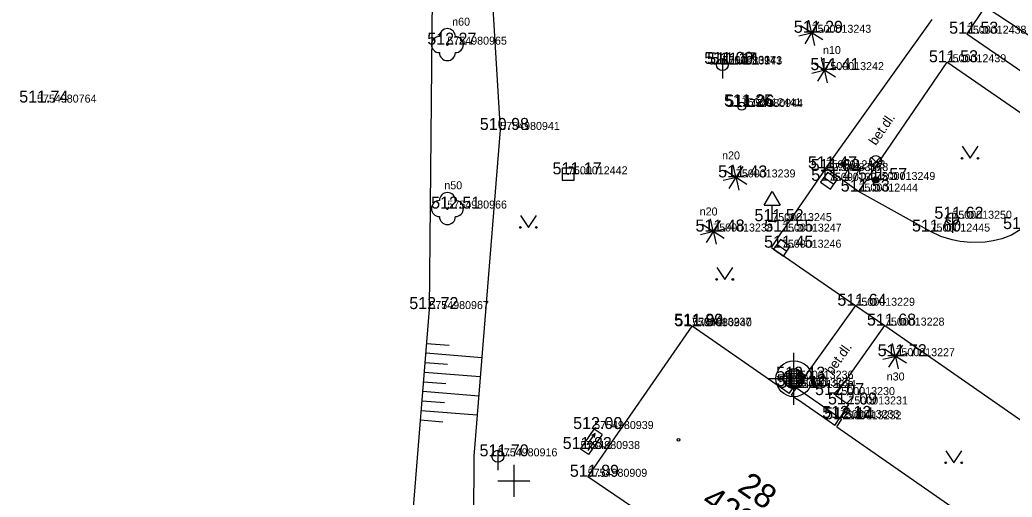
# Model space of a CAD drawing. Extents: x -669251 to -668549, y -1128351 to -1127698.
# Drawn here: x -669030.9 to -668968.9, y -1127851 to -1127821.2 of the extents above; entities that cross this region are included whole.
import ezdxf

# ---------------------------------------------------------------- set-up
doc = ezdxf.new("R2010")
doc.units = 0
for name, color, linetype in [('Vrstva 1', 7, 'Continuous'), ('Vrstva 10', 7, 'Continuous'), ('Vrstva 14', 7, 'Continuous'), ('Vrstva 15', 7, 'Continuous'), ('Vrstva 2', 7, 'Continuous'), ('Vrstva 22', 7, 'Continuous'), ('Vrstva 24', 7, 'Continuous'), ('Vrstva 26', 7, 'Continuous'), ('Vrstva 27', 7, 'Continuous'), ('Vrstva 28', 7, 'Continuous'), ('Vrstva 3', 7, 'Continuous'), ('Vrstva 33', 7, 'Continuous'), ('Vrstva 34', 7, 'Continuous'), ('Vrstva 35', 7, 'Continuous'), ('Vrstva 36', 7, 'Continuous'), ('Vrstva 40', 7, 'Continuous'), ('Vrstva 43', 7, 'Continuous'), ('Vrstva 44', 7, 'Continuous'), ('Vrstva 47', 7, 'Continuous'), ('Vrstva 5', 7, 'Continuous'), ('Vrstva 58', 7, 'Continuous'), ('Vrstva 6', 7, 'Continuous'), ('Vrstva 61', 7, 'Continuous')]:
    doc.layers.add(name, color=color, linetype=linetype)

msp = doc.modelspace()

# ---------------------------------------------------------------- linework, layer by layer
at = {"layer": 'Vrstva 1'}
for p, q in [((-668981.406, -1127822.003), (-668981.406, -1127822.003)), ((-668971.708, -1127822.059), (-668971.708, -1127822.059)), ((-669004.161, -1127822.744), (-669004.161, -1127822.744)), ((-668986.979, -1127823.945), (-668986.979, -1127823.945)), ((-668986.976, -1127823.985), (-668986.976, -1127823.985)), ((-668986.967, -1127823.978), (-668986.967, -1127823.978)), ((-668972.971, -1127823.843), (-668972.971, -1127823.843)), ((-668980.61, -1127824.335), (-668980.61, -1127824.335)), ((-669029.794, -1127826.363), (-669029.794, -1127826.363)), ((-668985.772, -1127826.592), (-668985.772, -1127826.592)), ((-668985.664, -1127826.638), (-668985.664, -1127826.638)), ((-669000.855, -1127828.073), (-669000.855, -1127828.073)), ((-668980.529, -1127830.465), (-668980.529, -1127830.465)), ((-668996.623, -1127830.845), (-668996.623, -1127830.845)), ((-668986.136, -1127831.039), (-668986.136, -1127831.039)), ((-668980.34, -1127830.637), (-668980.34, -1127830.637)), ((-668980.323, -1127831.251), (-668980.323, -1127831.251)), ((-668977.401, -1127831.199), (-668977.401, -1127831.199)), ((-668978.48, -1127831.921), (-668978.48, -1127831.921)), ((-669004.157, -1127832.983), (-669004.157, -1127832.983)), ((-668972.616, -1127833.619), (-668972.616, -1127833.619)), ((-668983.867, -1127833.77), (-668983.867, -1127833.77)), ((-668987.552, -1127834.418), (-668987.552, -1127834.418)), ((-668983.252, -1127834.425), (-668983.252, -1127834.425)), ((-668973.979, -1127834.42), (-668973.979, -1127834.42)), ((-668983.266, -1127835.429), (-668983.266, -1127835.429)), ((-668978.673, -1127839.056), (-668978.673, -1127839.056)), ((-669005.286, -1127839.263), (-669005.286, -1127839.263)), ((-668988.888, -1127840.303), (-668988.888, -1127840.303)), ((-668988.862, -1127840.338), (-668988.862, -1127840.338)), ((-668976.827, -1127840.295), (-668976.827, -1127840.295)), ((-668976.174, -1127842.207), (-668976.174, -1127842.207)), ((-668982.512, -1127843.612), (-668982.512, -1127843.612)), ((-668982.484, -1127844.079), (-668982.484, -1127844.079)), ((-668982.344, -1127844.184), (-668982.344, -1127844.184)), ((-668979.922, -1127844.635), (-668979.922, -1127844.635)), ((-668979.111, -1127845.221), (-668979.111, -1127845.221)), ((-668979.638, -1127846.064), (-668979.638, -1127846.064)), ((-668979.514, -1127846.15), (-668979.514, -1127846.15)), ((-668994.994, -1127846.756), (-668994.994, -1127846.756)), ((-669001.005, -1127848.461), (-669001.005, -1127848.461)), ((-668995.846, -1127848.005), (-668995.846, -1127848.005)), ((-668995.395, -1127849.739), (-668995.395, -1127849.739))]:
    msp.add_line(p, q, dxfattribs=at)
at = {"layer": 'Vrstva 10'}
for p, q in [((-668970.571, -1127820.351), (-668971.708, -1127822.059)), ((-668980.529, -1127830.465), (-668973.882, -1127821.169)), ((-668971.708, -1127822.059), (-668958.778, -1127830.987)), ((-668972.971, -1127823.843), (-668978.48, -1127831.921)), ((-668963.296, -1127830.498), (-668972.971, -1127823.843)), ((-668980.529, -1127830.465), (-668983.252, -1127834.425)), ((-668978.48, -1127831.921), (-668980.529, -1127830.465)), ((-668983.921, -1127835.421), (-668983.252, -1127834.425)), ((-668983.921, -1127835.421), (-668978.659, -1127839.036)), ((-668978.659, -1127839.036), (-668982.344, -1127844.184)), ((-668978.659, -1127839.036), (-668976.827, -1127840.295)), ((-668979.922, -1127844.635), (-668976.827, -1127840.295)), ((-668976.827, -1127840.295), (-668964.044, -1127849.199)), ((-668979.922, -1127844.635), (-668979.111, -1127845.221)), ((-668979.111, -1127845.221), (-668979.638, -1127846.064))]:
    msp.add_line(p, q, dxfattribs=at)
msp.add_lwpolyline([(-668963.296, -1127830.498), (-668965.81, -1127832.382), (-668968.324, -1127834.267), (-668968.933, -1127834.636), (-668969.524, -1127834.87), (-668970.075, -1127835.009), (-668970.575, -1127835.082), (-668971.469, -1127835.104), (-668972.137, -1127835.035), (-668972.628, -1127834.937), (-668973.332, -1127834.72), (-668973.979, -1127834.42), (-668976.23, -1127833.17), (-668978.48, -1127831.921)], dxfattribs=at)
at = {"layer": 'Vrstva 14'}
for p, q in [((-669005.286, -1127839.263), (-669004.995, -1127811.202)), ((-669001.902, -1127811.188), (-669000.855, -1127828.073)), ((-668970.571, -1127820.351), (-668957.386, -1127829.046)), ((-669000.855, -1127828.073), (-669002.505, -1127848.461)), ((-669007.556, -1127867.922), (-669005.286, -1127839.263)), ((-669002.505, -1127848.461), (-669002.591, -1127860.035))]:
    msp.add_line(p, q, dxfattribs=at)
at = {"layer": 'Vrstva 15'}
for p, q in [((-669005.456, -1127841.406), (-669004.056, -1127841.517)), ((-669005.503, -1127842.004), (-669002.005, -1127842.281)), ((-669005.55, -1127842.602), (-669004.152, -1127842.713)), ((-669005.598, -1127843.2), (-669002.102, -1127843.477)), ((-669005.645, -1127843.798), (-669004.247, -1127843.909)), ((-669005.693, -1127844.397), (-669002.198, -1127844.674)), ((-669005.74, -1127844.995), (-669004.343, -1127845.106)), ((-669005.787, -1127845.593), (-669002.295, -1127845.87)), ((-669005.835, -1127846.191), (-669004.438, -1127846.302))]:
    msp.add_line(p, q, dxfattribs=at)
at = {"layer": 'Vrstva 22'}
for p, q in [((-668981.414, -1127821.963), (-668981.586, -1127821.209)), ((-668981.44, -1127821.983), (-668982.096, -1127821.569)), ((-668980.972, -1127821.313), (-668981.386, -1127821.969)), ((-668981.366, -1127821.995), (-668980.612, -1127821.823)), ((-668982.2, -1127822.183), (-668981.446, -1127822.011)), ((-668981.426, -1127822.037), (-668981.84, -1127822.693)), ((-668981.398, -1127822.043), (-668981.226, -1127822.797)), ((-668980.716, -1127822.437), (-668981.372, -1127822.023)), ((-668980.618, -1127824.295), (-668980.79, -1127823.541)), ((-668980.176, -1127823.645), (-668980.59, -1127824.301)), ((-668980.644, -1127824.315), (-668981.3, -1127823.901)), ((-668980.57, -1127824.327), (-668979.816, -1127824.155)), ((-668981.404, -1127824.515), (-668980.65, -1127824.343)), ((-668980.63, -1127824.369), (-668981.044, -1127825.025)), ((-668980.602, -1127824.375), (-668980.43, -1127825.129)), ((-668979.92, -1127824.769), (-668980.576, -1127824.355)), ((-668986.144, -1127830.999), (-668986.316, -1127830.245)), ((-668985.702, -1127830.349), (-668986.116, -1127831.005)), ((-668986.93, -1127831.219), (-668986.176, -1127831.047)), ((-668986.17, -1127831.019), (-668986.826, -1127830.605)), ((-668986.156, -1127831.073), (-668986.57, -1127831.729)), ((-668986.128, -1127831.079), (-668985.956, -1127831.833)), ((-668985.446, -1127831.473), (-668986.102, -1127831.059)), ((-668986.096, -1127831.031), (-668985.342, -1127830.859)), ((-668987.56, -1127834.378), (-668987.732, -1127833.624)), ((-668987.586, -1127834.398), (-668988.242, -1127833.984)), ((-668987.118, -1127833.728), (-668987.532, -1127834.384)), ((-668987.512, -1127834.41), (-668986.758, -1127834.238)), ((-668988.346, -1127834.598), (-668987.592, -1127834.426)), ((-668987.572, -1127834.452), (-668987.986, -1127835.108)), ((-668987.544, -1127834.458), (-668987.372, -1127835.212)), ((-668986.862, -1127834.852), (-668987.518, -1127834.438)), ((-668976.182, -1127842.167), (-668976.354, -1127841.413)), ((-668975.74, -1127841.517), (-668976.154, -1127842.173)), ((-668976.968, -1127842.387), (-668976.214, -1127842.215)), ((-668976.208, -1127842.187), (-668976.864, -1127841.773)), ((-668976.194, -1127842.241), (-668976.608, -1127842.897)), ((-668976.166, -1127842.247), (-668975.994, -1127843.001)), ((-668975.484, -1127842.641), (-668976.14, -1127842.227)), ((-668976.134, -1127842.199), (-668975.38, -1127842.027))]:
    msp.add_line(p, q, dxfattribs=at)
for centre, radius in [((-668981.406, -1127822.003), 0.04), ((-669004.161, -1127822.744), 0.05), ((-668980.61, -1127824.335), 0.04), ((-668986.136, -1127831.039), 0.04), ((-669004.157, -1127832.983), 0.05), ((-668987.552, -1127834.418), 0.04), ((-668976.174, -1127842.207), 0.04)]:
    msp.add_circle(centre, radius, dxfattribs=at)
for centre, start, end in [((-669004.161, -1127822.244), 0, 180), ((-669004.661, -1127822.744), 90, 270), ((-669003.661, -1127822.744), 270, 90), ((-669004.161, -1127823.244), 180, 0), ((-669004.157, -1127832.483), 0, 180), ((-669004.657, -1127832.983), 90, 270), ((-669003.657, -1127832.983), 270, 90), ((-669004.157, -1127833.483), 180, 0)]:
    msp.add_arc(centre, 0.5, start, end, dxfattribs=at)
at = {"layer": 'Vrstva 24'}
for p, q in [((-668995.846, -1127848.005), (-668994.994, -1127846.756)), ((-668995.426, -1127847.752), (-668994.933, -1127847.029)), ((-668994.498, -1127847.094), (-668995.35, -1127848.343)), ((-668994.933, -1127847.029), (-668995.162, -1127847.169)), ((-668994.498, -1127847.094), (-668994.994, -1127846.756)), ((-668994.98, -1127847.293), (-668994.933, -1127847.029)), ((-668995.008, -1127847.583), (-668995.426, -1127847.752)), ((-668995.361, -1127848.1), (-668995.008, -1127847.583)), ((-668995.35, -1127848.343), (-668995.846, -1127848.005))]:
    msp.add_line(p, q, dxfattribs=at)
at = {"layer": 'Vrstva 26'}
msp.add_lwpolyline([(-668996.998, -1127831.22), (-668996.248, -1127831.22), (-668996.248, -1127830.47), (-668996.998, -1127830.47)], close=True, dxfattribs=at)
msp.add_circle((-668996.623, -1127830.845), 0.02, dxfattribs=at)
at = {"layer": 'Vrstva 27'}
for p, q in [((-668986.98, -1127823.615), (-668986.98, -1127824.865)), ((-668980.631, -1127831.037), (-668980.015, -1127831.465)), ((-668972.616, -1127833.244), (-668972.616, -1127834.494)), ((-668983.574, -1127835.215), (-668982.958, -1127835.643)), ((-669001.005, -1127848.086), (-669001.005, -1127849.336))]:
    msp.add_line(p, q, dxfattribs=at)
for points in [[(-668980.844, -1127831.344), (-668980.229, -1127831.772), (-668979.8, -1127831.156), (-668980.416, -1127830.728)], [(-668983.787, -1127835.522), (-668983.172, -1127835.95), (-668982.743, -1127835.334), (-668983.359, -1127834.906)]]:
    msp.add_lwpolyline(points, close=True, dxfattribs=at)
for centre in [(-668986.98, -1127823.99), (-668972.616, -1127833.619), (-669001.005, -1127848.461)]:
    msp.add_circle(centre, 0.375, dxfattribs=at)
at = {"layer": 'Vrstva 28'}
for p, q in [((-668986.022, -1127826.592), (-668986.522, -1127826.592)), ((-668985.522, -1127826.592), (-668985.022, -1127826.592))]:
    msp.add_line(p, q, dxfattribs=at)
msp.add_circle((-668985.772, -1127826.592), 0.25, dxfattribs=at)
at = {"layer": 'Vrstva 33'}
for p, q in [((-668977.666, -1127829.784), (-668977.136, -1127830.314)), ((-668977.666, -1127830.314), (-668977.136, -1127829.784)), ((-668977.401, -1127831.199), (-668977.401, -1127830.424))]:
    msp.add_line(p, q, dxfattribs=at)
for centre, radius in [((-668977.401, -1127830.049), 0.375), ((-668977.401, -1127831.199), 0.2), ((-668977.401, -1127831.199), 0.18), ((-668977.401, -1127831.199), 0.16), ((-668977.401, -1127831.199), 0.14), ((-668977.401, -1127831.199), 0.12), ((-668977.401, -1127831.199), 0.1), ((-668977.401, -1127831.199), 0.08), ((-668977.401, -1127831.199), 0.06), ((-668977.401, -1127831.199), 0.04), ((-668977.401, -1127831.199), 0.02)]:
    msp.add_circle(centre, radius, dxfattribs=at)
at = {"layer": 'Vrstva 34'}
for p, q in [((-668984.367, -1127832.77), (-668983.867, -1127831.92)), ((-668983.867, -1127831.92), (-668983.367, -1127832.77)), ((-668984.367, -1127832.77), (-668983.367, -1127832.77)), ((-668983.867, -1127833.77), (-668983.867, -1127832.77)), ((-668984.117, -1127833.77), (-668983.617, -1127833.77))]:
    msp.add_line(p, q, dxfattribs=at)
at = {"layer": 'Vrstva 35'}
for p, q in [((-668982.512, -1127842.987), (-668982.512, -1127841.987)), ((-668981.907, -1127843.456), (-668983.117, -1127843.456)), ((-668981.971, -1127843.299), (-668983.053, -1127843.299)), ((-668982.981, -1127843.199), (-668982.981, -1127844.025)), ((-668982.099, -1127843.143), (-668982.925, -1127843.143)), ((-668982.824, -1127843.07), (-668982.824, -1127844.154)), ((-668982.668, -1127843.007), (-668982.668, -1127844.217)), ((-668982.512, -1127842.987), (-668982.512, -1127844.237)), ((-668982.356, -1127843.007), (-668982.356, -1127844.217)), ((-668982.2, -1127843.07), (-668982.2, -1127844.154)), ((-668982.043, -1127843.199), (-668982.043, -1127844.025)), ((-668983.137, -1127843.612), (-668984.137, -1127843.612)), ((-668981.887, -1127843.612), (-668983.137, -1127843.612)), ((-668981.907, -1127843.768), (-668983.117, -1127843.768)), ((-668981.971, -1127843.925), (-668983.053, -1127843.925)), ((-668982.099, -1127844.081), (-668982.925, -1127844.081)), ((-668980.887, -1127843.612), (-668981.887, -1127843.612)), ((-668982.512, -1127845.237), (-668982.512, -1127844.237))]:
    msp.add_line(p, q, dxfattribs=at)
for radius in [1.125, 0.625]:
    msp.add_circle((-668982.512, -1127843.612), radius, dxfattribs=at)
at = {"layer": 'Vrstva 36'}
for p, q in [((-668972.011, -1127829.09), (-668971.511, -1127829.84)), ((-668971.511, -1127829.84), (-668971.011, -1127829.09)), ((-668999.6, -1127833.414), (-668999.1, -1127834.164)), ((-668999.1, -1127834.164), (-668998.6, -1127833.414)), ((-668987.332, -1127836.661), (-668986.832, -1127837.411)), ((-668986.832, -1127837.411), (-668986.332, -1127836.661)), ((-668973.034, -1127848.114), (-668972.534, -1127848.864)), ((-668972.534, -1127848.864), (-668972.034, -1127848.114))]:
    msp.add_line(p, q, dxfattribs=at)
for centre in [(-668972.011, -1127829.84), (-668971.011, -1127829.84), (-668999.6, -1127834.164), (-668998.6, -1127834.164), (-668987.333, -1127837.411), (-668986.333, -1127837.411), (-668973.034, -1127848.864), (-668972.034, -1127848.864)]:
    msp.add_circle(centre, 0.05, dxfattribs=at)
at = {"layer": 'Vrstva 5'}
for p, q in [((-668995.395, -1127849.739), (-668988.862, -1127840.338)), ((-668982.809, -1127844.547), (-668988.862, -1127840.338)), ((-668982.809, -1127844.547), (-668982.484, -1127844.079)), ((-668982.484, -1127844.079), (-668982.344, -1127844.184)), ((-668982.666, -1127844.647), (-668982.344, -1127844.184)), ((-668982.666, -1127844.647), (-668982.296, -1127844.904)), ((-668982.344, -1127844.184), (-668979.638, -1127846.064)), ((-668979.961, -1127846.528), (-668980.322, -1127846.277)), ((-668979.961, -1127846.528), (-668979.638, -1127846.064)), ((-668979.837, -1127846.614), (-668979.514, -1127846.15)), ((-668979.837, -1127846.614), (-668968.035, -1127854.821)), ((-668979.638, -1127846.064), (-668979.514, -1127846.15)), ((-668989.262, -1127853.878), (-668995.395, -1127849.739))]:
    msp.add_line(p, q, dxfattribs=at)
at = {"layer": 'Vrstva 58'}
msp.add_circle((-668989.729, -1127847.435), 0.0875, dxfattribs=at)
at = {"layer": 'Vrstva 6'}
msp.add_line((-668980.322, -1127846.277), (-668982.296, -1127844.904), dxfattribs=at)
at = {"layer": 'Vrstva 61'}
for p, q in [((-669000, -1127849), (-669000, -1127851)), ((-669001, -1127850), (-668999, -1127850))]:
    msp.add_line(p, q, dxfattribs=at)

# ---------------------------------------------------------------- texts
at = {"layer": 'Vrstva 2'}
for s, p in [('7500013243', (-668981.406, -1127822.003)), ('7500012438', (-668971.708, -1127822.059)), ('5754980965', (-669004.161, -1127822.744)), ('5754980943', (-668986.976, -1127823.985)), ('7500013241', (-668986.979, -1127823.945)), ('5754983173', (-668986.967, -1127823.978)), ('7500012439', (-668972.971, -1127823.843)), ('7500013242', (-668980.61, -1127824.335)), ('5754980764', (-669029.794, -1127826.363)), ('7500012441', (-668985.772, -1127826.592)), ('5754980944', (-668985.664, -1127826.638)), ('5754980941', (-669000.855, -1127828.073)), ('7500012442', (-668996.623, -1127830.845)), ('7500012443', (-668980.529, -1127830.465)), ('5754983178', (-668980.34, -1127830.637)), ('7500013239', (-668986.136, -1127831.039)), ('7500013248', (-668980.323, -1127831.251)), ('7500013249', (-668977.401, -1127831.199)), ('7500012444', (-668978.48, -1127831.921)), ('5754980966', (-669004.157, -1127832.983)), ('7500013245', (-668983.867, -1127833.77)), ('7500013250', (-668972.616, -1127833.619)), ('7500013238', (-668987.552, -1127834.418)), ('7500013247', (-668983.252, -1127834.425)), ('7500012445', (-668973.979, -1127834.42)), ('7500013246', (-668983.266, -1127835.429)), ('7500013229', (-668978.673, -1127839.056)), ('5754980967', (-669005.286, -1127839.263)), ('7500013237', (-668988.888, -1127840.303)), ('7500013228', (-668976.827, -1127840.295)), ('5754980940', (-668988.862, -1127840.338)), ('7500013227', (-668976.174, -1127842.207)), ('7500013236', (-668982.512, -1127843.612)), ('7500013235', (-668982.484, -1127844.079)), ('7500013234', (-668982.344, -1127844.184)), ('7500013230', (-668979.922, -1127844.635)), ('7500013231', (-668979.111, -1127845.221)), ('7500013233', (-668979.638, -1127846.064)), ('7500013232', (-668979.514, -1127846.15)), ('5754980939', (-668994.994, -1127846.756)), ('5754980938', (-668995.846, -1127848.005)), ('5754980916', (-669001.005, -1127848.461)), ('5754980909', (-668995.395, -1127849.739))]:
    msp.add_text(s, height=0.5, dxfattribs=at).set_placement(p)
at = {"layer": 'Vrstva 3'}
for s, p in [('511.29 ', (-668982.52, -1127822.003)), ('511.53 ', (-668972.818, -1127822.059)), ('512.27 ', (-669005.413, -1127822.744)), ('511.53 ', (-668974.081, -1127823.843)), ('511.09 ', (-668988.114, -1127823.945)), ('511.17 ', (-668987.935, -1127823.978)), ('511.11 ', (-668987.708, -1127823.985)), ('511.41 ', (-668981.484, -1127824.335)), ('511.74 ', (-669030.904, -1127826.363)), ('511.25 ', (-668986.882, -1127826.592)), ('511.26 ', (-668986.797, -1127826.638)), ('510.98 ', (-669002.131, -1127828.073)), ('511.47 ', (-668981.639, -1127830.465)), ('511.62 ', (-668981.464, -1127830.637)), ('511.17 ', (-668997.591, -1127830.845)), ('511.43 ', (-668987.246, -1127831.039)), ('511.47 ', (-668981.433, -1127831.251)), ('511.57 ', (-668978.511, -1127831.199)), ('511.53 ', (-668979.59, -1127831.921)), ('512.51 ', (-669005.172, -1127832.983)), ('511.62 ', (-668973.74, -1127833.619)), ('511.52 ', (-668984.977, -1127833.77)), ('511.64 ', (-668969.448, -1127834.267)), ('511.48 ', (-668988.662, -1127834.418)), ('511.55 ', (-668984.362, -1127834.425)), ('511.60 ', (-668975.139, -1127834.42)), ('511.45 ', (-668984.376, -1127835.429)), ('512.72 ', (-669006.538, -1127839.263)), ('511.64 ', (-668979.797, -1127839.056)), ('511.89 ', (-668990.002, -1127840.303)), ('511.94 ', (-668989.974, -1127840.338)), ('511.68 ', (-668977.951, -1127840.295)), ('511.72 ', (-668977.284, -1127842.207)), ('512.13 ', (-668983.622, -1127843.612)), ('512.12 ', (-668983.594, -1127844.079)), ('512.10 ', (-668983.49, -1127844.184)), ('512.07 ', (-668981.196, -1127844.635)), ('512.09 ', (-668980.387, -1127845.221)), ('512.12 ', (-668980.748, -1127846.064)), ('512.14 ', (-668980.624, -1127846.15)), ('512.00 ', (-668996.303, -1127846.756)), ('511.82 ', (-668996.956, -1127848.005)), ('511.70 ', (-669002.151, -1127848.461)), ('511.89 ', (-668996.509, -1127849.739))]:
    msp.add_text(s, height=0.75, dxfattribs=at).set_placement(p)
at = {"layer": 'Vrstva 40'}
for rotation, p in [(55.70696, (-668977.396, -1127829.088)), (54.50606, (-668980.125, -1127843.399))]:
    msp.add_text('bet.dl.', height=0.6, rotation=rotation, dxfattribs=at).set_placement(p)
at = {"layer": 'Vrstva 43'}
msp.add_text('4227', height=1.5, rotation=325.21066, dxfattribs=at).set_placement((-668988.361, -1127851.45))
at = {"layer": 'Vrstva 44'}
msp.add_text('28', height=1.5, rotation=325.21066, dxfattribs=at).set_placement((-668986.115, -1127850.576))
at = {"layer": 'Vrstva 47'}
for s, p in [('n60', (-669003.86, -1127821.558)), ('n10', (-668980.698, -1127823.33)), ('n20', (-668986.999, -1127829.914)), ('n50', (-669004.349, -1127831.778)), ('n20', (-668988.399, -1127833.416)), ('n30', (-668976.716, -1127843.722))]:
    msp.add_text(s, height=0.5, dxfattribs=at).set_placement(p)

doc.saveas('drawing.dxf')
